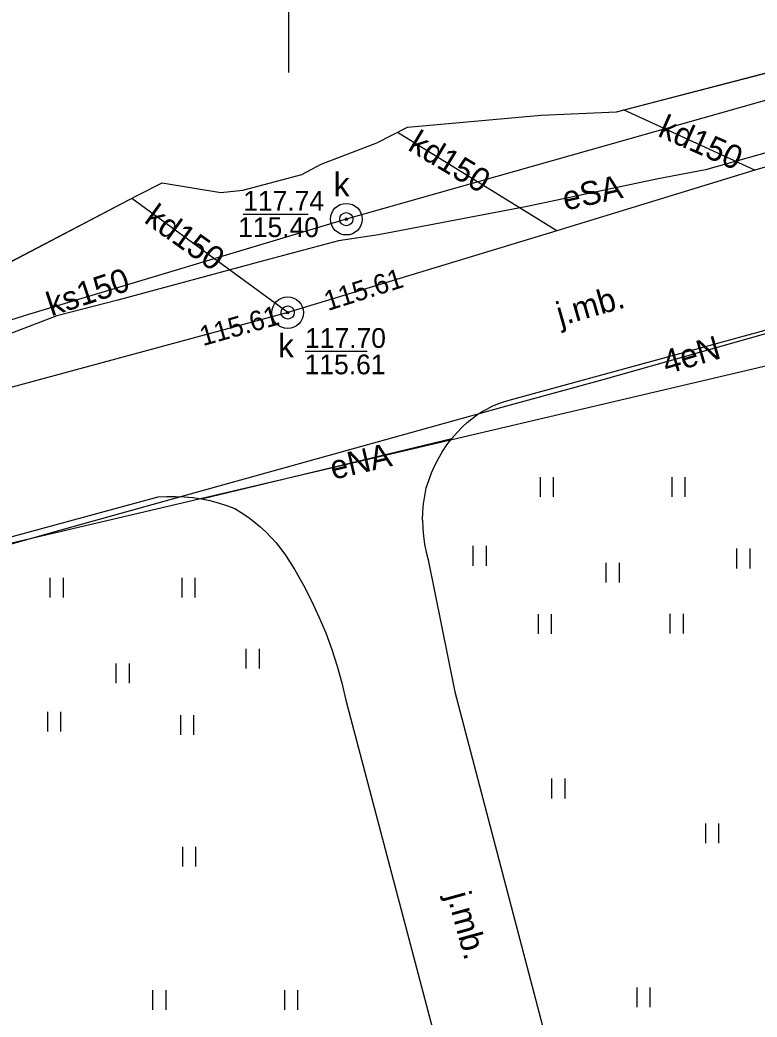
# Model space of a CAD drawing. Extents: x 6434771 to 6436222, y 5663454 to 5664782.
# Drawn here: x 6435389.81 to 6435417.79, y 5663859.17 to 5663897 of the extents above; entities that cross this region are included whole.
import ezdxf

# ---------------------------------------------------------------- set-up
doc = ezdxf.new("R2010")
doc.units = 0
for name, color, linetype in [('Warstwa 1', 7, 'Continuous'), ('Warstwa 10', 7, 'Continuous'), ('Warstwa 11', 7, 'Continuous'), ('Warstwa 12', 7, 'Continuous'), ('Warstwa 13', 7, 'Continuous'), ('Warstwa 14', 7, 'Continuous'), ('Warstwa 15', 7, 'Continuous'), ('Warstwa 4', 7, 'Continuous'), ('Warstwa 5', 7, 'Continuous'), ('Warstwa 6', 7, 'Continuous'), ('Warstwa 63', 7, 'Continuous'), ('Warstwa 7', 7, 'Continuous'), ('Warstwa 8', 7, 'Continuous')]:
    doc.layers.add(name, color=color, linetype=linetype)

msp = doc.modelspace()

# ---------------------------------------------------------------- linework, layer by layer
at = {"layer": 'Warstwa 1'}
msp.add_lwpolyline([(6435355.708, 5663879.109), (6435360.526, 5663876.441), (6435364.725, 5663883.781), (6435368.837, 5663883.121), (6435377.713, 5663883.554), (6435386.125, 5663886.083), (6435394.267, 5663890.335), (6435395.213, 5663890.813), (6435397.438, 5663890.456), (6435398.27, 5663890.536), (6435400.507, 5663891.129), (6435401.242, 5663891.521), (6435403.362, 5663892.335), (6435404.519, 5663892.931), (6435409.595, 5663893.38), (6435412.447, 5663893.515), (6435421.586, 5663895.885), (6435429.024, 5663899.776)], dxfattribs=at)
at = {"layer": 'Warstwa 10'}
msp.add_lwpolyline([(6435435.82, 5663897.12), (6435429.49, 5663895.204), (6435425.005, 5663893.888), (6435417.449, 5663891.772), (6435415.834, 5663891.31), (6435414.028, 5663890.971), (6435409.067, 5663889.926), (6435403.421, 5663888.843), (6435401.905, 5663888.621), (6435399.061, 5663887.863), (6435393.529, 5663886.371), (6435391.215, 5663885.774), (6435389.526, 5663885.122), (6435387.269, 5663884.265), (6435381.571, 5663881.929), (6435377.886, 5663880.534), (6435375.884, 5663879.812), (6435372.266, 5663878.727), (6435367.815, 5663877.271), (6435365.305, 5663876.244), (6435362.818, 5663875.192), (6435360.814, 5663874.4), (6435359.022, 5663874.085), (6435353.868, 5663873.017)], dxfattribs=at)
at = {"layer": 'Warstwa 12'}
for points in [[(6435463.66, 5663935.12), (6435460.91, 5663924.89), (6435462.44, 5663921.82), (6435441.07, 5663889.25), (6435356.73, 5663869.46), (6435331.52, 5663884.2), (6435330.44, 5663887.89), (6435327.58, 5663889.55), (6435318.31, 5663921.18), (6435313.59, 5663921.38), (6435311.91, 5663927.16), (6435315.9, 5663929.81), (6435312.06, 5663943.65)], [(6435439.665, 5663889.498), (6435437.773, 5663889.18), (6435427.206, 5663887.161), (6435423.329, 5663886.402), (6435422.197, 5663886.203), (6435418.694, 5663885.251), (6435411.939, 5663883.348), (6435408.275, 5663882.344), (6435397.724, 5663879.414), (6435391.364, 5663877.636), (6435383.243, 5663875.349), (6435379.254, 5663874.241), (6435376.591, 5663873.468), (6435375.411, 5663871.412), (6435371.712, 5663864.748), (6435371.655, 5663864.561)]]:
    msp.add_lwpolyline(points, dxfattribs=at)
at = {"layer": 'Warstwa 14'}
for p, q in [((6435398.287, 5663889.635), (6435400.75, 5663889.635)), ((6435400.633, 5663884.43), (6435402.988, 5663884.43))]:
    msp.add_line(p, q, dxfattribs=at)
for centre in [(6435402.197, 5663889.439), (6435399.974, 5663885.896), (6435399.974, 5663885.896), (6435399.974, 5663885.896)]:
    msp.add_circle(centre, 0.045, dxfattribs=at)
at = {"layer": 'Warstwa 15'}
for centre in [(6435402.197, 5663889.439), (6435399.974, 5663885.896)]:
    msp.add_circle(centre, 0.6, dxfattribs=at)
at = {"layer": 'Warstwa 4'}
for centre in [(6435402.197, 5663889.439), (6435399.974, 5663885.896)]:
    msp.add_circle(centre, 0.25, dxfattribs=at)
at = {"layer": 'Warstwa 5'}
for p, q in [((6435408.384, 5663882.574), (6435440.186, 5663891.275)), ((6435407.534, 5663882.238), (6435407.739, 5663882.34)), ((6435407.739, 5663882.34), (6435407.95, 5663882.43)), ((6435407.95, 5663882.43), (6435408.165, 5663882.508)), ((6435408.165, 5663882.508), (6435408.384, 5663882.574)), ((6435406.958, 5663881.866), (6435407.143, 5663882.001)), ((6435407.143, 5663882.001), (6435407.335, 5663882.125)), ((6435407.335, 5663882.125), (6435407.534, 5663882.238)), ((6435406.612, 5663881.565), (6435406.781, 5663881.72)), ((6435406.781, 5663881.72), (6435406.958, 5663881.866)), ((6435406.203, 5663881.116), (6435406.401, 5663881.346)), ((6435406.401, 5663881.346), (6435406.612, 5663881.565)), ((6435405.849, 5663880.624), (6435406.019, 5663880.875)), ((6435406.019, 5663880.875), (6435406.203, 5663881.116)), ((6435405.694, 5663880.363), (6435405.849, 5663880.624)), ((6435405.431, 5663879.815), (6435405.555, 5663880.093)), ((6435405.555, 5663880.093), (6435405.694, 5663880.363)), ((6435405.324, 5663879.531), (6435405.431, 5663879.815)), ((6435405.234, 5663879.242), (6435405.324, 5663879.531)), ((6435409.562, 5663878.908), (6435409.562, 5663879.658)), ((6435410.062, 5663878.908), (6435410.062, 5663879.658)), ((6435414.562, 5663878.908), (6435414.562, 5663879.658)), ((6435415.062, 5663878.908), (6435415.062, 5663879.658)), ((6435395.059, 5663878.904), (6435395.388, 5663878.923)), ((6435395.388, 5663878.923), (6435395.717, 5663878.925)), ((6435395.717, 5663878.925), (6435396.046, 5663878.91)), ((6435405.131, 5663878.638), (6435405.174, 5663878.942)), ((6435405.174, 5663878.942), (6435405.234, 5663879.242)), ((6435361.907, 5663869.914), (6435395.059, 5663878.904)), ((6435396.046, 5663878.91), (6435396.374, 5663878.878)), ((6435396.374, 5663878.878), (6435396.7, 5663878.829)), ((6435396.7, 5663878.829), (6435397.023, 5663878.764)), ((6435397.023, 5663878.764), (6435397.341, 5663878.682)), ((6435397.341, 5663878.682), (6435397.656, 5663878.583)), ((6435397.656, 5663878.583), (6435397.964, 5663878.469)), ((6435405.105, 5663878.333), (6435405.131, 5663878.638)), ((6435397.964, 5663878.469), (6435398.214, 5663878.316)), ((6435398.214, 5663878.316), (6435398.457, 5663878.151)), ((6435405.095, 5663878.026), (6435405.105, 5663878.333)), ((6435398.457, 5663878.151), (6435398.691, 5663877.974)), ((6435398.691, 5663877.974), (6435398.916, 5663877.786)), ((6435398.916, 5663877.786), (6435399.132, 5663877.588)), ((6435405.095, 5663878.026), (6435405.103, 5663877.72)), ((6435399.132, 5663877.588), (6435399.339, 5663877.379)), ((6435405.103, 5663877.72), (6435405.127, 5663877.414)), ((6435405.127, 5663877.414), (6435405.169, 5663877.11)), ((6435399.339, 5663877.379), (6435399.534, 5663877.16)), ((6435399.534, 5663877.16), (6435399.72, 5663876.933)), ((6435405.169, 5663877.11), (6435405.227, 5663876.809)), ((6435407.015, 5663876.292), (6435407.015, 5663877.042)), ((6435407.515, 5663876.292), (6435407.515, 5663877.042)), ((6435399.72, 5663876.933), (6435399.893, 5663876.696)), ((6435399.893, 5663876.696), (6435400.245, 5663876.131)), ((6435405.227, 5663876.809), (6435405.301, 5663876.511)), ((6435417.023, 5663876.194), (6435417.023, 5663876.944)), ((6435417.523, 5663876.194), (6435417.523, 5663876.944)), ((6435405.301, 5663876.511), (6435406.321, 5663871.508)), ((6435412.062, 5663875.658), (6435412.062, 5663876.408)), ((6435412.562, 5663875.658), (6435412.562, 5663876.408)), ((6435400.245, 5663876.131), (6435400.575, 5663875.553)), ((6435390.965, 5663875.085), (6435390.965, 5663875.835)), ((6435391.465, 5663875.085), (6435391.465, 5663875.835)), ((6435395.965, 5663875.085), (6435395.965, 5663875.835)), ((6435396.465, 5663875.085), (6435396.465, 5663875.835)), ((6435400.575, 5663875.553), (6435400.88, 5663874.962)), ((6435400.88, 5663874.962), (6435401.161, 5663874.358)), ((6435409.486, 5663873.709), (6435409.486, 5663874.459)), ((6435409.986, 5663873.709), (6435409.986, 5663874.459)), ((6435414.491, 5663873.718), (6435414.491, 5663874.468)), ((6435414.991, 5663873.718), (6435414.991, 5663874.468)), ((6435401.161, 5663874.358), (6435401.417, 5663873.744)), ((6435401.417, 5663873.744), (6435401.648, 5663873.12)), ((6435398.403, 5663872.396), (6435398.403, 5663873.146)), ((6435398.903, 5663872.396), (6435398.903, 5663873.146)), ((6435401.648, 5663873.12), (6435401.853, 5663872.487)), ((6435393.465, 5663871.835), (6435393.465, 5663872.585)), ((6435393.965, 5663871.835), (6435393.965, 5663872.585)), ((6435401.853, 5663872.487), (6435402.033, 5663871.846)), ((6435402.033, 5663871.846), (6435402.186, 5663871.198)), ((6435406.321, 5663871.508), (6435413.903, 5663842.645)), ((6435402.186, 5663871.198), (6435409.808, 5663842.314)), ((6435390.866, 5663870.003), (6435390.866, 5663870.753)), ((6435391.366, 5663870.003), (6435391.366, 5663870.753)), ((6435395.916, 5663869.873), (6435395.916, 5663870.623)), ((6435396.416, 5663869.873), (6435396.416, 5663870.623)), ((6435410.004, 5663867.469), (6435410.004, 5663868.219)), ((6435410.504, 5663867.469), (6435410.504, 5663868.219)), ((6435415.841, 5663865.767), (6435415.841, 5663866.517)), ((6435416.341, 5663865.767), (6435416.341, 5663866.517)), ((6435395.994, 5663864.881), (6435395.994, 5663865.631)), ((6435396.494, 5663864.881), (6435396.494, 5663865.631)), ((6435394.861, 5663859.444), (6435394.861, 5663860.194)), ((6435395.361, 5663859.444), (6435395.361, 5663860.194)), ((6435399.861, 5663859.444), (6435399.861, 5663860.194)), ((6435400.361, 5663859.444), (6435400.361, 5663860.194)), ((6435413.23, 5663859.544), (6435413.23, 5663860.294)), ((6435413.73, 5663859.544), (6435413.73, 5663860.294))]:
    msp.add_line(p, q, dxfattribs=at)
at = {"layer": 'Warstwa 6'}
for centre in [(6435402.197, 5663889.439), (6435399.974, 5663885.896)]:
    msp.add_circle(centre, 0.045, dxfattribs=at)
at = {"layer": 'Warstwa 63'}
msp.add_line((6435400, 5663905), (6435400, 5663895), dxfattribs=at)
at = {"layer": 'Warstwa 7'}
for points in [[(6435434.351, 5663901.79), (6435432.948, 5663899.298), (6435432.031, 5663897.899), (6435402.197, 5663889.439), (6435390.137, 5663885.82), (6435384.227, 5663883.964), (6435377.421, 5663881.796), (6435376.841, 5663881.598), (6435371.458, 5663879.765), (6435364.761, 5663877.53), (6435360.003, 5663875.987), (6435353.284, 5663873.848), (6435329.201, 5663865.434)], [(6435426.512, 5663893.826), (6435417.701, 5663891.302)], [(6435417.701, 5663891.302), (6435412.713, 5663893.584)], [(6435410.182, 5663888.993), (6435404.135, 5663892.733)], [(6435417.701, 5663891.302), (6435410.182, 5663888.993), (6435399.974, 5663885.896), (6435389.195, 5663882.973)], [(6435399.974, 5663885.896), (6435394.062, 5663890.228)]]:
    msp.add_lwpolyline(points, dxfattribs=at)
at = {"layer": 'Warstwa 8'}
for p, q in [((6435412.447, 5663893.515), (6435421.586, 5663895.885)), ((6435404.519, 5663892.931), (6435409.595, 5663893.38)), ((6435409.595, 5663893.38), (6435412.447, 5663893.515)), ((6435403.362, 5663892.335), (6435404.519, 5663892.931)), ((6435401.242, 5663891.521), (6435403.362, 5663892.335)), ((6435400.507, 5663891.129), (6435401.242, 5663891.521)), ((6435398.27, 5663890.536), (6435400.507, 5663891.129)), ((6435408.384, 5663882.574), (6435440.186, 5663891.275)), ((6435394.267, 5663890.335), (6435395.213, 5663890.813)), ((6435395.213, 5663890.813), (6435397.438, 5663890.456)), ((6435386.125, 5663886.083), (6435394.267, 5663890.335)), ((6435397.438, 5663890.456), (6435398.27, 5663890.536)), ((6435407.534, 5663882.238), (6435407.739, 5663882.34)), ((6435407.739, 5663882.34), (6435407.95, 5663882.43)), ((6435407.95, 5663882.43), (6435408.165, 5663882.508)), ((6435408.165, 5663882.508), (6435408.384, 5663882.574)), ((6435406.958, 5663881.866), (6435407.143, 5663882.001)), ((6435407.143, 5663882.001), (6435407.335, 5663882.125)), ((6435407.335, 5663882.125), (6435407.534, 5663882.238)), ((6435406.612, 5663881.565), (6435406.781, 5663881.72)), ((6435406.781, 5663881.72), (6435406.958, 5663881.866)), ((6435406.203, 5663881.116), (6435406.401, 5663881.346)), ((6435406.401, 5663881.346), (6435406.612, 5663881.565)), ((6435396.7, 5663878.829), (6435406.203, 5663881.116)), ((6435396.7, 5663878.829), (6435406.203, 5663881.116)), ((6435405.849, 5663880.624), (6435406.019, 5663880.875)), ((6435406.019, 5663880.875), (6435406.203, 5663881.116)), ((6435405.694, 5663880.363), (6435405.849, 5663880.624)), ((6435405.431, 5663879.815), (6435405.555, 5663880.093)), ((6435405.555, 5663880.093), (6435405.694, 5663880.363)), ((6435405.324, 5663879.531), (6435405.431, 5663879.815)), ((6435405.234, 5663879.242), (6435405.324, 5663879.531)), ((6435395.059, 5663878.904), (6435395.388, 5663878.923)), ((6435395.388, 5663878.923), (6435395.717, 5663878.925)), ((6435395.717, 5663878.925), (6435396.046, 5663878.91)), ((6435405.131, 5663878.638), (6435405.174, 5663878.942)), ((6435405.174, 5663878.942), (6435405.234, 5663879.242)), ((6435361.907, 5663869.914), (6435395.059, 5663878.904)), ((6435396.046, 5663878.91), (6435396.374, 5663878.878)), ((6435396.374, 5663878.878), (6435396.7, 5663878.829)), ((6435396.7, 5663878.829), (6435397.023, 5663878.764)), ((6435397.023, 5663878.764), (6435397.341, 5663878.682)), ((6435397.341, 5663878.682), (6435397.656, 5663878.583)), ((6435397.656, 5663878.583), (6435397.964, 5663878.469)), ((6435405.105, 5663878.333), (6435405.131, 5663878.638)), ((6435397.964, 5663878.469), (6435398.214, 5663878.316)), ((6435398.214, 5663878.316), (6435398.457, 5663878.151)), ((6435405.095, 5663878.026), (6435405.105, 5663878.333)), ((6435398.457, 5663878.151), (6435398.691, 5663877.974)), ((6435398.691, 5663877.974), (6435398.916, 5663877.786)), ((6435398.916, 5663877.786), (6435399.132, 5663877.588)), ((6435405.095, 5663878.026), (6435405.103, 5663877.72)), ((6435399.132, 5663877.588), (6435399.339, 5663877.379)), ((6435405.103, 5663877.72), (6435405.127, 5663877.414)), ((6435405.127, 5663877.414), (6435405.169, 5663877.11)), ((6435399.339, 5663877.379), (6435399.534, 5663877.16)), ((6435399.534, 5663877.16), (6435399.72, 5663876.933)), ((6435405.169, 5663877.11), (6435405.227, 5663876.809)), ((6435399.72, 5663876.933), (6435399.893, 5663876.696)), ((6435399.893, 5663876.696), (6435400.245, 5663876.131)), ((6435405.227, 5663876.809), (6435405.301, 5663876.511)), ((6435405.301, 5663876.511), (6435406.321, 5663871.508)), ((6435400.245, 5663876.131), (6435400.575, 5663875.553)), ((6435400.575, 5663875.553), (6435400.88, 5663874.962)), ((6435400.88, 5663874.962), (6435401.161, 5663874.358)), ((6435401.161, 5663874.358), (6435401.417, 5663873.744)), ((6435401.417, 5663873.744), (6435401.648, 5663873.12)), ((6435401.648, 5663873.12), (6435401.853, 5663872.487)), ((6435401.853, 5663872.487), (6435402.033, 5663871.846)), ((6435402.033, 5663871.846), (6435402.186, 5663871.198)), ((6435406.321, 5663871.508), (6435413.903, 5663842.645)), ((6435402.186, 5663871.198), (6435409.808, 5663842.314))]:
    msp.add_line(p, q, dxfattribs=at)

# ---------------------------------------------------------------- texts
at = {"layer": 'Warstwa 11'}
msp.add_text('eSA', height=0.9, rotation=12.5879, dxfattribs=at).set_placement((6435410.516, 5663889.762))
at = {"layer": 'Warstwa 13'}
for s, rotation, p in [('4eN', 16.421, (6435414.353, 5663883.55)), ('eNA', 13.2067, (6435401.699, 5663879.55))]:
    msp.add_text(s, height=0.9, rotation=rotation, dxfattribs=at).set_placement(p)
at = {"layer": 'Warstwa 14'}
for s, p in [('115.40', (6435398.093, 5663888.76)), ('115.61', (6435400.618, 5663883.555))]:
    msp.add_text(s, height=0.75, dxfattribs=at).set_placement(p)
for rotation, p in [(17.5669, (6435401.498, 5663885.952)), (15.8595, (6435396.759, 5663884.621))]:
    msp.add_text('115.61', height=0.75, rotation=rotation, dxfattribs=at).set_placement(p)
at = {"layer": 'Warstwa 5'}
for p in [(6435401.719, 5663890.305), (6435399.61, 5663884.192)]:
    msp.add_text('k', height=0.9, dxfattribs=at).set_placement(p)
at = {"layer": 'Warstwa 6'}
for s, p in [('117.74', (6435398.286, 5663889.76)), ('117.70', (6435400.634, 5663884.555))]:
    msp.add_text(s, height=0.75, dxfattribs=at).set_placement(p)
at = {"layer": 'Warstwa 7'}
for s, rotation, p in [('kd150', 336.1028, (6435413.976, 5663892.607)), ('kd150', 328.9523, (6435404.491, 5663892.087)), ('kd150', 324.4488, (6435394.484, 5663889.341)), ('ks150', 18.3404, (6435391.004, 5663885.747))]:
    msp.add_text(s, height=0.9, rotation=rotation, dxfattribs=at).set_placement(p)
at = {"layer": 'Warstwa 8'}
for rotation, p in [(15.9913, (6435410.323, 5663885.382)), (285.4075, (6435406.013, 5663863.793))]:
    msp.add_text('j.mb.', height=0.9, rotation=rotation, dxfattribs=at).set_placement(p)

doc.saveas('drawing.dxf')
